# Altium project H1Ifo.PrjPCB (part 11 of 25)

## Sheet IfoIsc5B.SchDoc: D1800185
size C; Engineer: Daniel Sigg; DocumentNumber: 10; Revision: 4; SheetNumber: 10; SheetTotal: 11
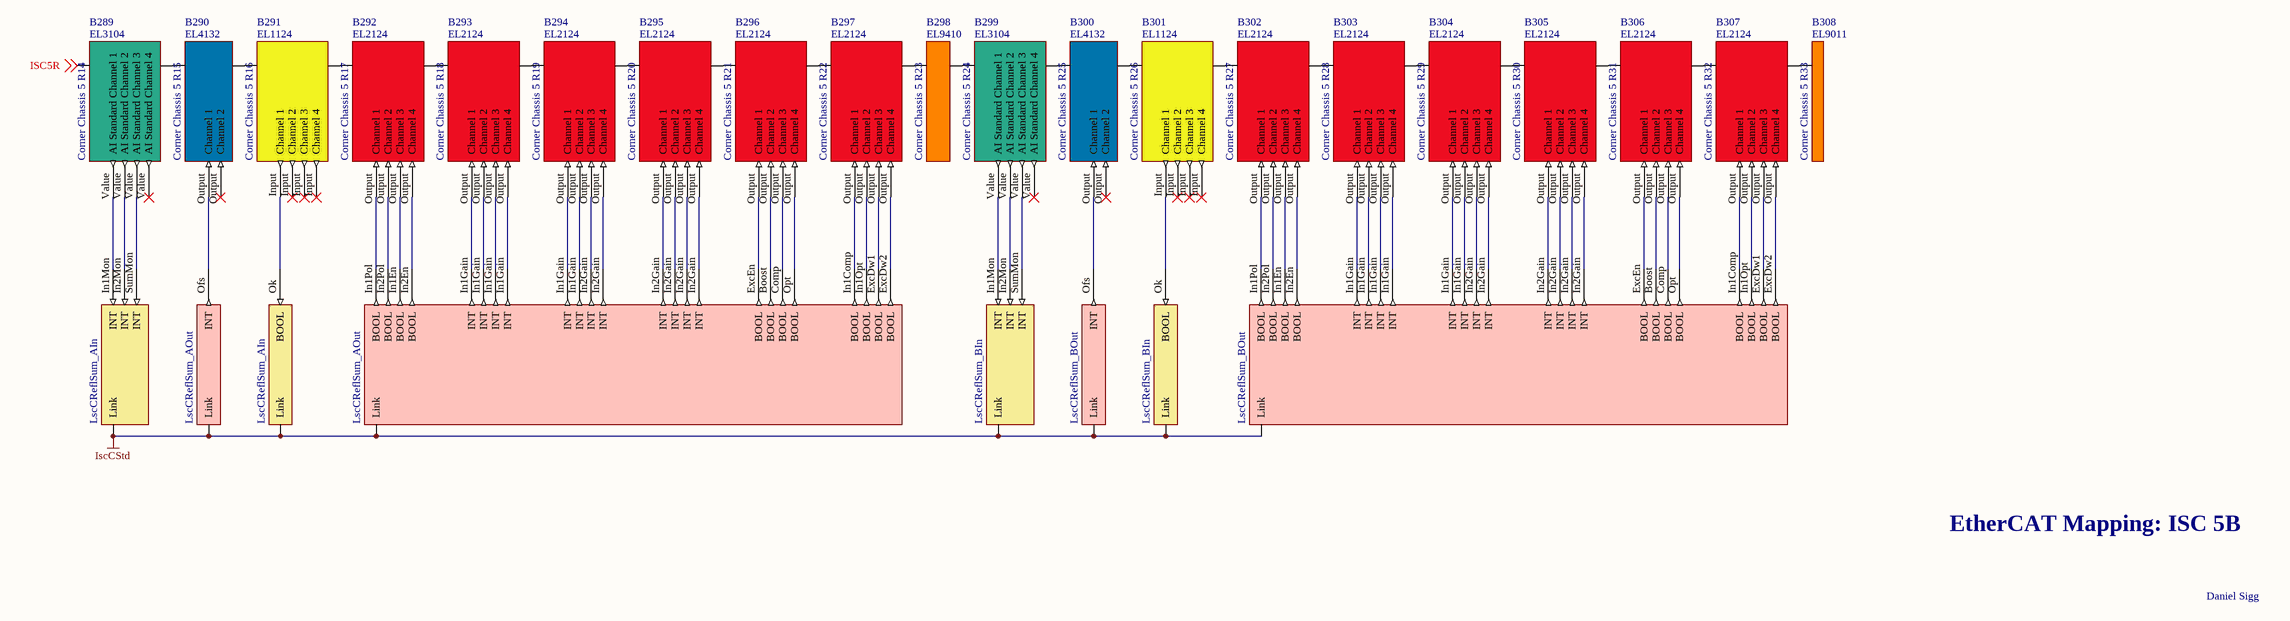
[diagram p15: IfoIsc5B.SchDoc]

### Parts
B289  Corner Chassis 5 R14  Part Number: EL3104  (mechanical)
B290  Corner Chassis 5 R15  Part Number: EL4132  (mechanical)
B291  Corner Chassis 5 R16  Part Number: EL1124  (mechanical)
B292  Corner Chassis 5 R17  Part Number: EL2124  (mechanical)
B293  Corner Chassis 5 R18  Part Number: EL2124  (mechanical)
B294  Corner Chassis 5 R19  Part Number: EL2124  (mechanical)
B295  Corner Chassis 5 R20  Part Number: EL2124  (mechanical)
B296  Corner Chassis 5 R21  Part Number: EL2124  (mechanical)
B297  Corner Chassis 5 R22  Part Number: EL2124  (mechanical)
B298  Corner Chassis 5 R23  Part Number: EL9410  (mechanical)
B299  Corner Chassis 5 R24  Part Number: EL3104  (mechanical)
B300  Corner Chassis 5 R25  Part Number: EL4132  (mechanical)
B301  Corner Chassis 5 R26  Part Number: EL1124  (mechanical)
B302  Corner Chassis 5 R27  Part Number: EL2124  (mechanical)
B303  Corner Chassis 5 R28  Part Number: EL2124  (mechanical)
B304  Corner Chassis 5 R29  Part Number: EL2124  (mechanical)
B305  Corner Chassis 5 R30  Part Number: EL2124  (mechanical)
B306  Corner Chassis 5 R31  Part Number: EL2124  (mechanical)
B307  Corner Chassis 5 R32  Part Number: EL2124  (mechanical)
B308  Corner Chassis 5 R33  Part Number: EL9011  (mechanical)
V211  LscCReflSum_AIn  (parts A,B of 2)  (no BOM)
V212  LscCReflSum_AOut  (parts A,B of 2)  (no BOM)
V213  LscCReflSum_BIn  (parts A,B of 2)  (no BOM)
V214  LscCReflSum_BOut  (parts A,B of 2)  (no BOM)

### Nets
IscCStd: V211.1(Link) V211.?1(Link) V212.2(Link) V212.?1(Link) V213.1(Link) V213.?1(Link) V214.2(Link) V214.?1(Link)
ISC5R: B289.Ebus(A) ; off-sheet ISC5R
NetB289_Ebus: B289.Ebus(B) B290.Ebus(A)
NetB289_Value: B289.Value(AI_Standard_Channel_1) V211.In1Mon(INT)
NetB289_Value: B289.Value(AI_Standard_Channel_2) V211.In2Mon(INT)  [a separate net that carries the same name]
NetB289_Value: B289.Value(AI_Standard_Channel_3) V211.SumMon(INT)  [a separate net that carries the same name]
NetB290_Ebus: B290.Ebus(B) B291.Ebus(A)
NetB290_Output: B290.Output(Channel_1) V212.Ofs(INT)
NetB291_Ebus: B291.Ebus(B) B292.Ebus(A)
NetB291_Input: B291.Input(Channel_1) V211.Ok(BOOL)
NetB292_Ebus: B292.Ebus(B) B293.Ebus(A)
NetB292_Output: B292.Output(Channel_1) V212.In1Pol(BOOL)
NetB292_Output: B292.Output(Channel_2) V212.In2Pol(BOOL)  [a separate net that carries the same name]
NetB292_Output: B292.Output(Channel_3) V212.In1En(BOOL)  [a separate net that carries the same name]
NetB292_Output: B292.Output(Channel_4) V212.In2En(BOOL)  [a separate net that carries the same name]
NetB293_Ebus: B293.Ebus(B) B294.Ebus(A)
NetB293_Output: B293.Output(Channel_1) V212.In1Gain(INT)
NetB293_Output: B293.Output(Channel_2) V212.In1Gain(INT)  [a separate net that carries the same name]
NetB293_Output: B293.Output(Channel_3) V212.In1Gain(INT)  [a separate net that carries the same name]
NetB293_Output: B293.Output(Channel_4) V212.In1Gain(INT)  [a separate net that carries the same name]
NetB294_Ebus: B294.Ebus(B) B295.Ebus(A)
NetB294_Output: B294.Output(Channel_1) V212.In1Gain(INT)
NetB294_Output: B294.Output(Channel_2) V212.In1Gain(INT)  [a separate net that carries the same name]
NetB294_Output: B294.Output(Channel_3) V212.In2Gain(INT)  [a separate net that carries the same name]
NetB294_Output: B294.Output(Channel_4) V212.In2Gain(INT)  [a separate net that carries the same name]
NetB295_Ebus: B295.Ebus(B) B296.Ebus(A)
NetB295_Output: B295.Output(Channel_1) V212.In2Gain(INT)
NetB295_Output: B295.Output(Channel_2) V212.In2Gain(INT)  [a separate net that carries the same name]
NetB295_Output: B295.Output(Channel_3) V212.In2Gain(INT)  [a separate net that carries the same name]
NetB295_Output: B295.Output(Channel_4) V212.In2Gain(INT)  [a separate net that carries the same name]
NetB296_Ebus: B296.Ebus(B) B297.Ebus(A)
NetB296_Output: B296.Output(Channel_1) V212.ExcEn(BOOL)
NetB296_Output: B296.Output(Channel_2) V212.Boost(BOOL)  [a separate net that carries the same name]
NetB296_Output: B296.Output(Channel_3) V212.Comp(BOOL)  [a separate net that carries the same name]
NetB296_Output: B296.Output(Channel_4) V212.Opt(BOOL)  [a separate net that carries the same name]
NetB297_Ebus: B297.Ebus(B) B298.Ebus(A)
NetB297_Output: B297.Output(Channel_1) V212.In1Comp(BOOL)
NetB297_Output: B297.Output(Channel_2) V212.In1Opt(BOOL)  [a separate net that carries the same name]
NetB297_Output: B297.Output(Channel_3) V212.ExcDw1(BOOL)  [a separate net that carries the same name]
NetB297_Output: B297.Output(Channel_4) V212.ExcDw2(BOOL)  [a separate net that carries the same name]
NetB298_Ebus: B298.Ebus(B) B299.Ebus(A)
NetB299_Ebus: B299.Ebus(B) B300.Ebus(A)
NetB299_Value: B299.Value(AI_Standard_Channel_1) V213.In1Mon(INT)
NetB299_Value: B299.Value(AI_Standard_Channel_2) V213.In2Mon(INT)  [a separate net that carries the same name]
NetB299_Value: B299.Value(AI_Standard_Channel_3) V213.SumMon(INT)  [a separate net that carries the same name]
NetB300_Ebus: B300.Ebus(B) B301.Ebus(A)
NetB300_Output: B300.Output(Channel_1) V214.Ofs(INT)
NetB301_Ebus: B301.Ebus(B) B302.Ebus(A)
NetB301_Input: B301.Input(Channel_1) V213.Ok(BOOL)
NetB302_Ebus: B302.Ebus(B) B303.Ebus(A)
NetB302_Output: B302.Output(Channel_1) V214.In1Pol(BOOL)
NetB302_Output: B302.Output(Channel_2) V214.In2Pol(BOOL)  [a separate net that carries the same name]
NetB302_Output: B302.Output(Channel_3) V214.In1En(BOOL)  [a separate net that carries the same name]
NetB302_Output: B302.Output(Channel_4) V214.In2En(BOOL)  [a separate net that carries the same name]
NetB303_Ebus: B303.Ebus(B) B304.Ebus(A)
NetB303_Output: B303.Output(Channel_1) V214.In1Gain(INT)
NetB303_Output: B303.Output(Channel_2) V214.In1Gain(INT)  [a separate net that carries the same name]
NetB303_Output: B303.Output(Channel_3) V214.In1Gain(INT)  [a separate net that carries the same name]
NetB303_Output: B303.Output(Channel_4) V214.In1Gain(INT)  [a separate net that carries the same name]
NetB304_Ebus: B304.Ebus(B) B305.Ebus(A)
NetB304_Output: B304.Output(Channel_1) V214.In1Gain(INT)
NetB304_Output: B304.Output(Channel_2) V214.In1Gain(INT)  [a separate net that carries the same name]
NetB304_Output: B304.Output(Channel_3) V214.In2Gain(INT)  [a separate net that carries the same name]
NetB304_Output: B304.Output(Channel_4) V214.In2Gain(INT)  [a separate net that carries the same name]
NetB305_Ebus: B305.Ebus(B) B306.Ebus(A)
NetB305_Output: B305.Output(Channel_1) V214.In2Gain(INT)
NetB305_Output: B305.Output(Channel_2) V214.In2Gain(INT)  [a separate net that carries the same name]
NetB305_Output: B305.Output(Channel_3) V214.In2Gain(INT)  [a separate net that carries the same name]
NetB305_Output: B305.Output(Channel_4) V214.In2Gain(INT)  [a separate net that carries the same name]
NetB306_Ebus: B306.Ebus(B) B307.Ebus(A)
NetB306_Output: B306.Output(Channel_1) V214.ExcEn(BOOL)
NetB306_Output: B306.Output(Channel_2) V214.Boost(BOOL)  [a separate net that carries the same name]
NetB306_Output: B306.Output(Channel_3) V214.Comp(BOOL)  [a separate net that carries the same name]
NetB306_Output: B306.Output(Channel_4) V214.Opt(BOOL)  [a separate net that carries the same name]
NetB307_Ebus: B307.Ebus(B) B308.Ebus(A)
NetB307_Output: B307.Output(Channel_1) V214.In1Comp(BOOL)
NetB307_Output: B307.Output(Channel_2) V214.In1Opt(BOOL)  [a separate net that carries the same name]
NetB307_Output: B307.Output(Channel_3) V214.ExcDw1(BOOL)  [a separate net that carries the same name]
NetB307_Output: B307.Output(Channel_4) V214.ExcDw2(BOOL)  [a separate net that carries the same name]

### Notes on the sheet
- EtherCAT Mapping: ISC 5B
- Daniel Sigg

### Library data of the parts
B289 = TerminalEL3104: EtherCAT Terminal EL3104 4-chn Analog Input; Rail: Right; BoxNextB: FBYTHKHY; BoxPrev: CGVGPFCF; PortPrevFull: 1234/B; PortPrevShort: B; Fullname: TIID^Vertex ISC (EtherCAT)^Corner Chassis 5 R0 (EK1100)^Corner Chassis 5 R14 (EL3104); BoxAddr: 1235; Disabled: False
B290 = TerminalEL4132: EtherCAT Terminal EL4132 2-chn Analog Ouput; Rail: Right; BoxNextB: TMVYBIWV; BoxPrev: TSURHCSJ; PortPrevFull: 1235/B; PortPrevShort: B; Fullname: TIID^Vertex ISC (EtherCAT)^Corner Chassis 5 R0 (EK1100)^Corner Chassis 5 R15 (EL4132); BoxAddr: 1236; Disabled: False
B291 = TerminalEL1124: EtherCAT Terminal EL1124 4-chn Digital Input; Rail: Right; BoxNextB: ABTJCILK; BoxPrev: FBYTHKHY; PortPrevFull: 1236/B; PortPrevShort: B; Fullname: TIID^Vertex ISC (EtherCAT)^Corner Chassis 5 R0 (EK1100)^Corner Chassis 5 R16 (EL1124); BoxAddr: 1237; Disabled: False
B292 = TerminalEL2124: EtherCAT Terminal EL2124 4-chn Digital Ouput; Rail: Right; BoxNextB: USYVCCJA; BoxPrev: TMVYBIWV; PortPrevFull: 1237/B; PortPrevShort: B; Fullname: TIID^Vertex ISC (EtherCAT)^Corner Chassis 5 R0 (EK1100)^Corner Chassis 5 R17 (EL2124); BoxAddr: 1238; Disabled: False
B293 = TerminalEL2124: EtherCAT Terminal EL2124 4-chn Digital Ouput; Rail: Right; BoxNextB: CMPSNXUT; BoxPrev: ABTJCILK; PortPrevFull: 1238/B; PortPrevShort: B; Fullname: TIID^Vertex ISC (EtherCAT)^Corner Chassis 5 R0 (EK1100)^Corner Chassis 5 R18 (EL2124); BoxAddr: 1239; Disabled: False
B294 = TerminalEL2124: EtherCAT Terminal EL2124 4-chn Digital Ouput; Rail: Right; BoxNextB: OUNMTUHQ; BoxPrev: USYVCCJA; PortPrevFull: 1239/B; PortPrevShort: B; Fullname: TIID^Vertex ISC (EtherCAT)^Corner Chassis 5 R0 (EK1100)^Corner Chassis 5 R19 (EL2124); BoxAddr: 1240; Disabled: False
B295 = TerminalEL2124: EtherCAT Terminal EL2124 4-chn Digital Ouput; Rail: Right; BoxNextB: KQXHJWYC; BoxPrev: CMPSNXUT; PortPrevFull: 1240/B; PortPrevShort: B; Fullname: TIID^Vertex ISC (EtherCAT)^Corner Chassis 5 R0 (EK1100)^Corner Chassis 5 R20 (EL2124); BoxAddr: 1241; Disabled: False
B296 = TerminalEL2124: EtherCAT Terminal EL2124 4-chn Digital Ouput; Rail: Right; BoxNextB: AANUUWXV; BoxPrev: OUNMTUHQ; PortPrevFull: 1241/B; PortPrevShort: B; Fullname: TIID^Vertex ISC (EtherCAT)^Corner Chassis 5 R0 (EK1100)^Corner Chassis 5 R21 (EL2124); BoxAddr: 1242; Disabled: False
B297 = TerminalEL2124: EtherCAT Terminal EL2124 4-chn Digital Ouput; Rail: Right; BoxNextB: FXHMVIQL; BoxPrev: KQXHJWYC; PortPrevFull: 1242/B; PortPrevShort: B; Fullname: TIID^Vertex ISC (EtherCAT)^Corner Chassis 5 R0 (EK1100)^Corner Chassis 5 R22 (EL2124); BoxAddr: 1243; Disabled: False
B298 = TerminalEL9410: EtherCAT Terminal EL9410 Power; Rail: Right; BoxNextB: LGPOEEBF; BoxPrev: AANUUWXV; PortPrevFull: 1243/B; PortPrevShort: B; Fullname: TIID^Vertex ISC (EtherCAT)^Corner Chassis 5 R0 (EK1100)^Corner Chassis 5 R23 (EL9410); BoxAddr: 1244; Disabled: False
B299 = TerminalEL3104: EtherCAT Terminal EL3104 4-chn Analog Input; Rail: Right; BoxNextB: VREJYUEC; BoxPrev: FXHMVIQL; PortPrevFull: 1244/B; PortPrevShort: B; Fullname: TIID^Vertex ISC (EtherCAT)^Corner Chassis 5 R0 (EK1100)^Corner Chassis 5 R24 (EL3104); BoxAddr: 1245; Disabled: False
B300 = TerminalEL4132: EtherCAT Terminal EL4132 2-chn Analog Ouput; Rail: Right; BoxNextB: BYMTCIWL; BoxPrev: LGPOEEBF; PortPrevFull: 1245/B; PortPrevShort: B; Fullname: TIID^Vertex ISC (EtherCAT)^Corner Chassis 5 R0 (EK1100)^Corner Chassis 5 R25 (EL4132); BoxAddr: 1246; Disabled: False
B301 = TerminalEL1124: EtherCAT Terminal EL1124 4-chn Digital Input; Rail: Right; BoxNextB: WRMXGODM; BoxPrev: VREJYUEC; PortPrevFull: 1246/B; PortPrevShort: B; Fullname: TIID^Vertex ISC (EtherCAT)^Corner Chassis 5 R0 (EK1100)^Corner Chassis 5 R26 (EL1124); BoxAddr: 1247; Disabled: False
B302 = TerminalEL2124: EtherCAT Terminal EL2124 4-chn Digital Ouput; Rail: Right; BoxNextB: WJPMTAEU; BoxPrev: BYMTCIWL; PortPrevFull: 1247/B; PortPrevShort: B; Fullname: TIID^Vertex ISC (EtherCAT)^Corner Chassis 5 R0 (EK1100)^Corner Chassis 5 R27 (EL2124); BoxAddr: 1248; Disabled: False
B303 = TerminalEL2124: EtherCAT Terminal EL2124 4-chn Digital Ouput; Rail: Right; BoxNextB: BTAIVAAV; BoxPrev: WRMXGODM; PortPrevFull: 1248/B; PortPrevShort: B; Fullname: TIID^Vertex ISC (EtherCAT)^Corner Chassis 5 R0 (EK1100)^Corner Chassis 5 R28 (EL2124); BoxAddr: 1249; Disabled: False
B304 = TerminalEL2124: EtherCAT Terminal EL2124 4-chn Digital Ouput; Rail: Right; BoxNextB: YDTLCXYC; BoxPrev: WJPMTAEU; PortPrevFull: 1249/B; PortPrevShort: B; Fullname: TIID^Vertex ISC (EtherCAT)^Corner Chassis 5 R0 (EK1100)^Corner Chassis 5 R29 (EL2124); BoxAddr: 1250; Disabled: False
B305 = TerminalEL2124: EtherCAT Terminal EL2124 4-chn Digital Ouput; Rail: Right; BoxNextB: QLJTFPDQ; BoxPrev: BTAIVAAV; PortPrevFull: 1250/B; PortPrevShort: B; Fullname: TIID^Vertex ISC (EtherCAT)^Corner Chassis 5 R0 (EK1100)^Corner Chassis 5 R30 (EL2124); BoxAddr: 1251; Disabled: False
B306 = TerminalEL2124: EtherCAT Terminal EL2124 4-chn Digital Ouput; Rail: Right; BoxNextB: DAMFTACO; BoxPrev: YDTLCXYC; PortPrevFull: 1251/B; PortPrevShort: B; Fullname: TIID^Vertex ISC (EtherCAT)^Corner Chassis 5 R0 (EK1100)^Corner Chassis 5 R31 (EL2124); BoxAddr: 1252; Disabled: False
B307 = TerminalEL2124: EtherCAT Terminal EL2124 4-chn Digital Ouput; Rail: Right; BoxNextB: PUULPQDR; BoxPrev: QLJTFPDQ; PortPrevFull: 1252/B; PortPrevShort: B; Fullname: TIID^Vertex ISC (EtherCAT)^Corner Chassis 5 R0 (EK1100)^Corner Chassis 5 R32 (EL2124); BoxAddr: 1253; Disabled: False
B308 = TerminalEL9011: EtherCAT Terminal EL9011 End; BoxType: TerminalPassive; Rail: Right; BoxPrev: DAMFTACO; PortPrevShort: B; Fullname: TIID^Vertex ISC (EtherCAT)^Corner Chassis 5 R0 (EK1100)^Corner Chassis 5 R33 (EL9011); Disabled: False
V211 V213 = SummingNode_SummingNodeInStruct: SummingNodeInStruct; BoxType: Variable; Instance: H1IscCorner Instance; PLC: H1IscCorner; Task: IscCStd
V212 V214 = SummingNode_SummingNodeOutStruct: SummingNodeOutStruct; BoxType: Variable; Instance: H1IscCorner Instance; PLC: H1IscCorner; Task: IscCStd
